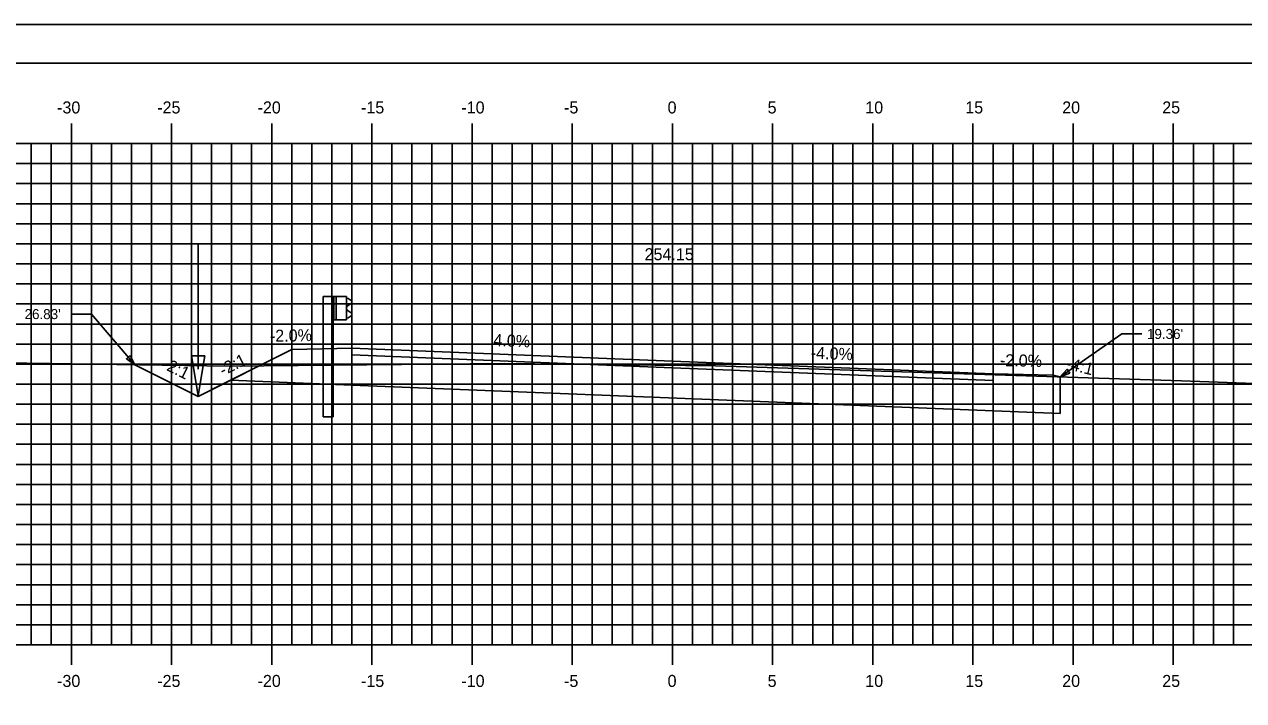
# Model space of a CAD drawing. Extents: x 1160718 to 1173142, y 616002 to 617630.
# Drawn here: x 1170373.6 to 1170434.4, y 616690.1 to 616723.9 of the extents above; entities that cross this region are included whole.
import ezdxf

# ---------------------------------------------------------------- set-up
doc = ezdxf.new("R2010")
doc.units = 0
for name, color, linetype in [('ANNOTATION', 7, 'Continuous'), ('BORDER', 7, 'Continuous'), ('D_Drainage_Ditch_Line', 7, 'Continuous'), ('D_Guardrail_Beam_Lt', 7, 'Continuous'), ('D_Roadway_Centerline', 7, 'Continuous'), ('D_Roadway_Centerline_Text', 7, 'Continuous'), ('D_Roadway_Edge_Shoulder', 7, 'Continuous'), ('D_Roadway_Edge_TW', 7, 'Continuous'), ('D_Roadway_Pavement', 7, 'Continuous'), ('D_Roadway_SlopeLines', 7, 'Continuous'), ('D_Roadway_SubGrade', 7, 'Continuous'), ('H_V ANNOTATION', 7, 'Continuous'), ('MAJOR', 7, 'Continuous'), ('MINOR', 7, 'Continuous'), ('PLOT BOUNDARY', 7, 'Continuous'), ('S_Roadway_Centerline', 7, 'Continuous'), ('SHADING', 7, 'Continuous')]:
    doc.layers.add(name, color=color, linetype=linetype)

msp = doc.modelspace()

# ---------------------------------------------------------------- linework, layer by layer
at = {"layer": 'ANNOTATION'}
for p, q in [((1170375.907, 616709.422), (1170376.907, 616709.422)), ((1170379.075, 616706.896), (1170376.907, 616709.422)), ((1170425.266, 616706.286), (1170428.342, 616708.433)), ((1170429.342, 616708.433), (1170428.342, 616708.433))]:
    msp.add_line(p, q, dxfattribs=at)
for points in [[(1170378.844, 616707.357), (1170379.075, 616706.896), (1170378.655, 616707.194)], [(1170425.748, 616706.47), (1170425.266, 616706.286), (1170425.605, 616706.675)]]:
    msp.add_lwpolyline(points, close=True, dxfattribs=at)
at = {"layer": 'BORDER'}
msp.add_line((1170490.907, 616721.928), (1170330.907, 616721.928), dxfattribs=at)
at = {"layer": 'D_Drainage_Ditch_Line'}
msp.add_line((1170382.236, 616706.68), (1170382.236, 616712.924), dxfattribs=at)
msp.add_lwpolyline([(1170381.908, 616707.337), (1170382.564, 616707.337), (1170382.236, 616705.368)], close=True, dxfattribs=at)
at = {"layer": 'D_Guardrail_Beam_Lt'}
for p, q in [((1170388.479, 616710.299), (1170388.479, 616704.299)), ((1170388.95, 616710.299), (1170388.479, 616710.299)), ((1170389.637, 616710.299), (1170388.95, 616710.299)), ((1170388.95, 616710.299), (1170388.95, 616709.133)), ((1170389.012, 616710.299), (1170389.012, 616709.133)), ((1170389.117, 616710.299), (1170389.117, 616709.133)), ((1170389.637, 616709.133), (1170389.637, 616710.299)), ((1170389.637, 616710.216), (1170389.712, 616710.201)), ((1170389.871, 616709.952), (1170389.676, 616709.815)), ((1170389.727, 616710.195), (1170389.871, 616710.095)), ((1170389.642, 616709.751), (1170389.642, 616709.681)), ((1170389.676, 616709.616), (1170389.871, 616709.48)), ((1170389.871, 616709.337), (1170389.727, 616709.237)), ((1170388.95, 616709.133), (1170389.637, 616709.133)), ((1170388.971, 616704.299), (1170388.971, 616709.133)), ((1170389.712, 616709.231), (1170389.637, 616709.216)), ((1170388.971, 616704.299), (1170388.479, 616704.299))]:
    msp.add_line(p, q, dxfattribs=at)
for centre, major_axis, start_param, end_param in [((1170389.704, 616710.161), (0.0417, 0), 0.959931, 1.376053), ((1170389.821, 616710.023), (0.0877, 0), 5.323254, 7.243116), ((1170389.721, 616709.751), (-0.0789, 0), 5.323254, 6.283185), ((1170389.721, 616709.681), (-0.0789, 0), 6.283185, 7.243116), ((1170389.821, 616709.409), (0.0877, 0), 5.323254, 7.243116), ((1170389.704, 616709.271), (0.0417, 0), 4.907132, 5.323254)]:
    msp.add_ellipse(centre, major_axis=major_axis, ratio=0.995501, start_param=start_param, end_param=end_param, dxfattribs=at)
at = {"layer": 'D_Roadway_Centerline'}
for points in [[(1170379.075, 616706.896), (1170382.231, 616705.318), (1170386.907, 616707.656)], [(1170382.919, 616705.662), (1170386.907, 616707.656), (1170389.907, 616707.716), (1170405.907, 616707.076), (1170421.907, 616706.436), (1170424.907, 616706.376), (1170425.266, 616706.286)]]:
    msp.add_lwpolyline(points, dxfattribs=at)
at = {"layer": 'D_Roadway_Edge_Shoulder'}
for points in [[(1170389.907, 616707.716), (1170389.907, 616707.383)], [(1170421.907, 616706.436), (1170421.907, 616706.103)]]:
    msp.add_lwpolyline(points, dxfattribs=at)
at = {"layer": 'D_Roadway_Edge_TW'}
msp.add_lwpolyline([(1170421.907, 616706.103), (1170421.907, 616706.436), (1170405.907, 616707.076), (1170389.907, 616707.716), (1170389.907, 616707.383), (1170405.907, 616706.743)], close=True, dxfattribs=at)
at = {"layer": 'D_Roadway_Pavement'}
msp.add_lwpolyline([(1170421.907, 616706.103), (1170421.907, 616706.103), (1170405.907, 616706.743), (1170389.907, 616707.383), (1170389.907, 616707.383), (1170405.907, 616706.743)], close=True, dxfattribs=at)
for points in [[(1170389.907, 616707.383), (1170389.907, 616707.383)], [(1170389.907, 616707.383), (1170389.907, 616707.383)], [(1170421.907, 616706.103), (1170421.907, 616706.103)], [(1170421.907, 616706.103), (1170421.907, 616706.103)]]:
    msp.add_lwpolyline(points, dxfattribs=at)
at = {"layer": 'D_Roadway_SlopeLines'}
for points in [[(1170386.907, 616707.656), (1170382.231, 616705.318)], [(1170424.907, 616706.376), (1170425.266, 616706.286)]]:
    msp.add_lwpolyline(points, dxfattribs=at)
at = {"layer": 'D_Roadway_SubGrade'}
for p, q in [((1170386.907, 616707.656), (1170382.919, 616705.662)), ((1170389.907, 616707.716), (1170386.907, 616707.656)), ((1170389.907, 616705.883), (1170389.907, 616707.716)), ((1170405.907, 616706.743), (1170389.907, 616707.383)), ((1170389.907, 616707.383), (1170389.907, 616705.883)), ((1170421.907, 616706.103), (1170405.907, 616706.743)), ((1170421.907, 616706.436), (1170424.907, 616706.376)), ((1170421.907, 616704.603), (1170421.907, 616706.436)), ((1170424.907, 616706.376), (1170425.266, 616706.286)), ((1170425.266, 616706.286), (1170425.266, 616704.468)), ((1170421.907, 616704.603), (1170421.907, 616706.103))]:
    msp.add_line(p, q, dxfattribs=at)
at = {"layer": 'MAJOR'}
for p, q in [((1170375.907, 616718.93), (1170375.907, 616717.928)), ((1170380.907, 616718.93), (1170380.907, 616717.928)), ((1170385.907, 616718.93), (1170385.907, 616717.928)), ((1170390.907, 616718.93), (1170390.907, 616717.928)), ((1170395.907, 616718.93), (1170395.907, 616717.928)), ((1170400.907, 616718.93), (1170400.907, 616717.928)), ((1170405.907, 616718.93), (1170405.907, 616717.928)), ((1170410.907, 616718.93), (1170410.907, 616717.928)), ((1170415.907, 616718.93), (1170415.907, 616717.928)), ((1170420.907, 616718.93), (1170420.907, 616717.928)), ((1170425.907, 616718.93), (1170425.907, 616717.928)), ((1170430.907, 616718.93), (1170430.907, 616717.928)), ((1170335.907, 616717.928), (1170475.907, 616717.928)), ((1170335.907, 616717.928), (1170475.907, 616717.928)), ((1170375.907, 616692.928), (1170375.907, 616717.928)), ((1170380.907, 616692.928), (1170380.907, 616717.928)), ((1170385.907, 616692.928), (1170385.907, 616717.928)), ((1170390.907, 616692.928), (1170390.907, 616717.928)), ((1170395.907, 616692.928), (1170395.907, 616717.928)), ((1170400.907, 616692.928), (1170400.907, 616717.928)), ((1170405.907, 616692.928), (1170405.907, 616717.928)), ((1170410.907, 616692.928), (1170410.907, 616717.928)), ((1170415.907, 616692.928), (1170415.907, 616717.928)), ((1170420.907, 616692.928), (1170420.907, 616717.928)), ((1170425.907, 616692.928), (1170425.907, 616717.928)), ((1170430.907, 616692.928), (1170430.907, 616717.928)), ((1170335.907, 616712.928), (1170475.907, 616712.928)), ((1170335.907, 616707.928), (1170475.907, 616707.928)), ((1170335.907, 616702.928), (1170475.907, 616702.928)), ((1170335.907, 616697.928), (1170475.907, 616697.928)), ((1170335.907, 616692.928), (1170475.907, 616692.928)), ((1170335.907, 616692.928), (1170475.907, 616692.928)), ((1170375.907, 616691.926), (1170375.907, 616692.928)), ((1170380.907, 616691.926), (1170380.907, 616692.928)), ((1170385.907, 616691.926), (1170385.907, 616692.928)), ((1170390.907, 616691.926), (1170390.907, 616692.928)), ((1170395.907, 616691.926), (1170395.907, 616692.928)), ((1170400.907, 616691.926), (1170400.907, 616692.928)), ((1170405.907, 616691.926), (1170405.907, 616692.928)), ((1170410.907, 616691.926), (1170410.907, 616692.928)), ((1170415.907, 616691.926), (1170415.907, 616692.928)), ((1170420.907, 616691.926), (1170420.907, 616692.928)), ((1170425.907, 616691.926), (1170425.907, 616692.928)), ((1170430.907, 616691.926), (1170430.907, 616692.928))]:
    msp.add_line(p, q, dxfattribs=at)
at = {"layer": 'MINOR'}
for p, q in [((1170373.907, 616692.928), (1170373.907, 616717.928)), ((1170374.907, 616692.928), (1170374.907, 616717.928)), ((1170376.907, 616692.928), (1170376.907, 616717.928)), ((1170377.907, 616692.928), (1170377.907, 616717.928)), ((1170378.907, 616692.928), (1170378.907, 616717.928)), ((1170379.907, 616692.928), (1170379.907, 616717.928)), ((1170381.907, 616692.928), (1170381.907, 616717.928)), ((1170382.907, 616692.928), (1170382.907, 616717.928)), ((1170383.907, 616692.928), (1170383.907, 616717.928)), ((1170384.907, 616692.928), (1170384.907, 616717.928)), ((1170386.907, 616692.928), (1170386.907, 616717.928)), ((1170387.907, 616692.928), (1170387.907, 616717.928)), ((1170388.907, 616692.928), (1170388.907, 616717.928)), ((1170389.907, 616692.928), (1170389.907, 616717.928)), ((1170391.907, 616692.928), (1170391.907, 616717.928)), ((1170392.907, 616692.928), (1170392.907, 616717.928)), ((1170393.907, 616692.928), (1170393.907, 616717.928)), ((1170394.907, 616692.928), (1170394.907, 616717.928)), ((1170396.907, 616692.928), (1170396.907, 616717.928)), ((1170397.907, 616692.928), (1170397.907, 616717.928)), ((1170398.907, 616692.928), (1170398.907, 616717.928)), ((1170399.907, 616692.928), (1170399.907, 616717.928)), ((1170401.907, 616692.928), (1170401.907, 616717.928)), ((1170402.907, 616692.928), (1170402.907, 616717.928)), ((1170403.907, 616692.928), (1170403.907, 616717.928)), ((1170404.907, 616692.928), (1170404.907, 616717.928)), ((1170406.907, 616692.928), (1170406.907, 616717.928)), ((1170407.907, 616692.928), (1170407.907, 616717.928)), ((1170408.907, 616692.928), (1170408.907, 616717.928)), ((1170409.907, 616692.928), (1170409.907, 616717.928)), ((1170411.907, 616692.928), (1170411.907, 616717.928)), ((1170412.907, 616692.928), (1170412.907, 616717.928)), ((1170413.907, 616692.928), (1170413.907, 616717.928)), ((1170414.907, 616692.928), (1170414.907, 616717.928)), ((1170416.907, 616692.928), (1170416.907, 616717.928)), ((1170417.907, 616692.928), (1170417.907, 616717.928)), ((1170418.907, 616692.928), (1170418.907, 616717.928)), ((1170419.907, 616692.928), (1170419.907, 616717.928)), ((1170421.907, 616692.928), (1170421.907, 616717.928)), ((1170422.907, 616692.928), (1170422.907, 616717.928)), ((1170423.907, 616692.928), (1170423.907, 616717.928)), ((1170424.907, 616692.928), (1170424.907, 616717.928)), ((1170426.907, 616692.928), (1170426.907, 616717.928)), ((1170427.907, 616692.928), (1170427.907, 616717.928)), ((1170428.907, 616692.928), (1170428.907, 616717.928)), ((1170429.907, 616692.928), (1170429.907, 616717.928)), ((1170431.907, 616692.928), (1170431.907, 616717.928)), ((1170432.907, 616692.928), (1170432.907, 616717.928)), ((1170433.907, 616692.928), (1170433.907, 616717.928)), ((1170335.907, 616716.928), (1170475.907, 616716.928)), ((1170335.907, 616715.928), (1170475.907, 616715.928)), ((1170335.907, 616714.928), (1170475.907, 616714.928)), ((1170335.907, 616713.928), (1170475.907, 616713.928)), ((1170335.907, 616711.928), (1170475.907, 616711.928)), ((1170335.907, 616710.928), (1170475.907, 616710.928)), ((1170335.907, 616709.928), (1170475.907, 616709.928)), ((1170335.907, 616708.928), (1170475.907, 616708.928)), ((1170335.907, 616706.928), (1170475.907, 616706.928)), ((1170335.907, 616705.928), (1170475.907, 616705.928)), ((1170335.907, 616704.928), (1170475.907, 616704.928)), ((1170335.907, 616703.928), (1170475.907, 616703.928)), ((1170335.907, 616701.928), (1170475.907, 616701.928)), ((1170335.907, 616700.928), (1170475.907, 616700.928)), ((1170335.907, 616699.928), (1170475.907, 616699.928)), ((1170335.907, 616698.928), (1170475.907, 616698.928)), ((1170335.907, 616696.928), (1170475.907, 616696.928)), ((1170335.907, 616695.928), (1170475.907, 616695.928)), ((1170335.907, 616694.928), (1170475.907, 616694.928)), ((1170335.907, 616693.928), (1170475.907, 616693.928))]:
    msp.add_line(p, q, dxfattribs=at)
at = {"layer": 'PLOT BOUNDARY'}
msp.add_lwpolyline([(1170322.814, 616613.869), (1170492.814, 616613.869), (1170492.814, 616723.869), (1170322.814, 616723.869)], close=True, dxfattribs=at)
at = {"layer": 'S_Roadway_Centerline'}
msp.add_lwpolyline([(1170335.907, 616704.811), (1170340.482, 616705.097), (1170353.832, 616706.596), (1170369.172, 616707.043), (1170383.793, 616706.826), (1170397.533, 616706.967), (1170408.058, 616706.838), (1170431.31, 616706.092), (1170436.791, 616705.902), (1170444.734, 616703.686), (1170447.414, 616702.847), (1170450.297, 616703.605), (1170461.415, 616706.922), (1170461.842, 616707), (1170461.983, 616707.027), (1170462.09, 616707.047), (1170462.469, 616707.105), (1170463.299, 616707.229), (1170464.21, 616707.258), (1170466.107, 616707.306), (1170475.907, 616707.564)], dxfattribs=at)
at = {"layer": 'SHADING'}
msp.add_lwpolyline([(1170383.845, 616706.125), (1170389.907, 616705.883), (1170425.266, 616704.468)], dxfattribs=at)

# ---------------------------------------------------------------- texts
at = {"layer": 'ANNOTATION'}
for s, p in [("26.83'", (1170373.574, 616709.172)), ("19.36'", (1170429.592, 616708.183))]:
    msp.add_text(s, height=0.5, dxfattribs=at).set_placement(p)
for s, rotation, p in [('-2.0%', 1.14576, (1170385.823, 616708.036)), ('4.0%', 357.70939, (1170396.963, 616707.835)), ('-4.0%', 357.70939, (1170412.803, 616707.201)), ('2:1', 333.43495, (1170380.62, 616706.642)), ('-2:1', 26.56505, (1170383.476, 616706.324)), ('-2.0%', 358.85424, (1170422.25, 616706.829)), ('-4:1', 345.96376, (1170425.491, 616706.703))]:
    msp.add_text(s, height=0.6, rotation=rotation, dxfattribs=at).set_placement(p)
at = {"layer": 'D_Roadway_Centerline'}
for s, p in [('C', (1170405.902, 616707.076)), ('L', (1170405.907, 616707.069))]:
    msp.add_text(s, height=0.0146, dxfattribs=at).set_placement(p)
at = {"layer": 'D_Roadway_Centerline_Text'}
msp.add_text('254.15', height=0.6, dxfattribs=at).set_placement((1170404.518, 616712.108))
at = {"layer": 'H_V ANNOTATION'}
for s, p in [('-30', (1170375.195, 616719.428)), ('-25', (1170380.193, 616719.428)), ('-20', (1170385.201, 616719.428)), ('-15', (1170390.364, 616719.428)), ('-10', (1170395.372, 616719.428)), ('-5', (1170400.498, 616719.428)), ('0', (1170405.666, 616719.428)), ('5', (1170410.658, 616719.428)), ('10', (1170415.532, 616719.428)), ('15', (1170420.524, 616719.428)), ('20', (1170425.361, 616719.428)), ('25', (1170430.353, 616719.428)), ('-30', (1170375.195, 616690.828)), ('-25', (1170380.193, 616690.828)), ('-20', (1170385.201, 616690.828)), ('-15', (1170390.364, 616690.828)), ('-10', (1170395.372, 616690.828)), ('-5', (1170400.498, 616690.828)), ('0', (1170405.666, 616690.828)), ('5', (1170410.658, 616690.828)), ('10', (1170415.532, 616690.828)), ('15', (1170420.524, 616690.828)), ('20', (1170425.361, 616690.828)), ('25', (1170430.353, 616690.828))]:
    msp.add_text(s, height=0.6, dxfattribs=at).set_placement(p)

doc.saveas('drawing.dxf')
